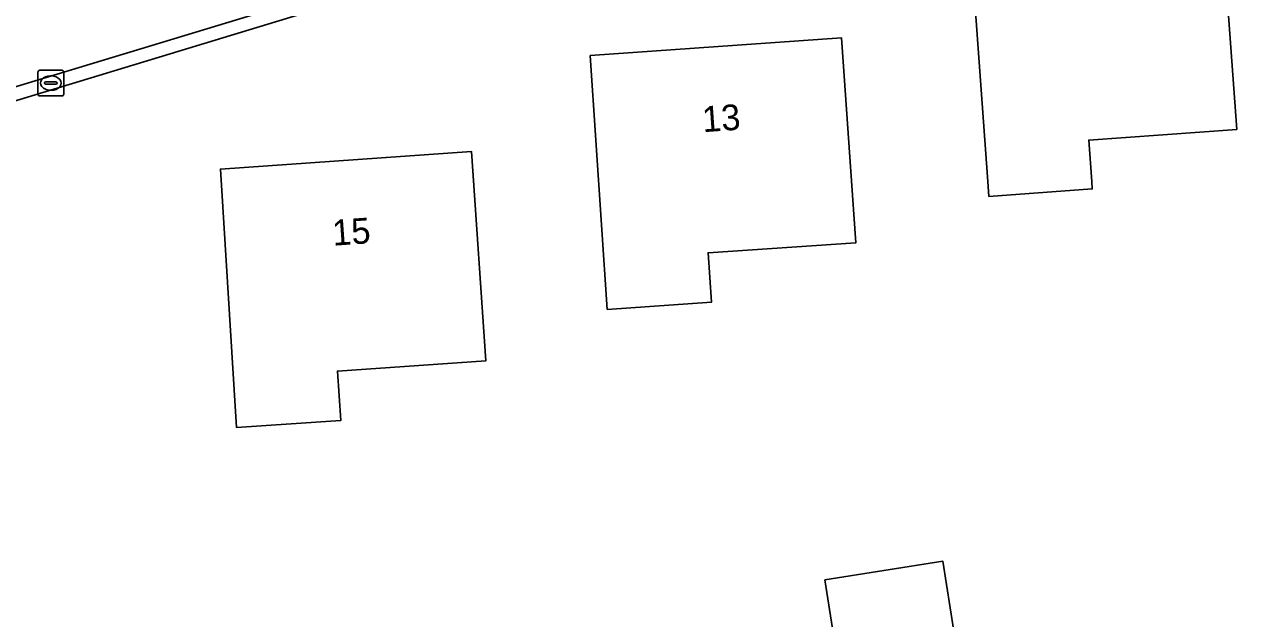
# Model space of a CAD drawing. Extents: x 162661 to 163484, y 380247 to 381230.
# Drawn here: x 162936.22 to 162983.36, y 380733 to 380756.11 of the extents above; entities that cross this region are included whole.
import ezdxf

# ---------------------------------------------------------------- set-up
doc = ezdxf.new("R2010")
doc.units = 0
for name, color, linetype in [('IMGEO_Erf', 7, 'Continuous'), ('IMGEO_Kolk', 7, 'Continuous'), ('IMGEO_Pand', 7, 'Continuous'), ('IMGEO_Pand_nummerreeks', 7, 'Continuous'), ('IMGEO_Rijbaan_lokaal_gesloten', 7, 'Continuous'), ('IMGEO_Rijbaan_lokaal_open', 7, 'Continuous')]:
    doc.layers.add(name, color=color, linetype=linetype)

msp = doc.modelspace()

# ---------------------------------------------------------------- linework, layer by layer
at = {"layer": 'IMGEO_Erf'}
for points in [[(162973.731, 380749.423), (162973.689, 380750), (162973.017, 380759.297), (162982.788, 380760.004), (162983.365, 380752.025), (162977.61, 380751.608), (162977.729, 380750), (162977.75, 380749.714)], [(162958.892, 380745.029), (162958.226, 380754.895), (162967.998, 380755.581), (162968.557, 380747.619), (162962.812, 380747.229), (162962.943, 380745.304)], [(162948.397, 380742.631), (162948.527, 380740.706), (162944.477, 380740.431), (162943.85, 380750.482), (162953.611, 380751.168), (162954.164, 380743.023)], [(162967.354, 380734.516), (162971.941, 380735.24), (162972.514, 380731.609), (162969.108, 380731.072), (162968.872, 380732.568), (162967.691, 380732.382)]]:
    msp.add_lwpolyline(points, close=True, dxfattribs=at)
msp.add_lwpolyline([(162954.012, 380758.66), (162897.8, 380741.576), (162880.446, 380736.315), (162878.841, 380735.907), (162876.106, 380735.042)], dxfattribs=at)
at = {"layer": 'IMGEO_Kolk'}
for p, q in [((162936.756, 380753.4), (162936.756, 380754.252)), ((162936.831, 380754.326), (162937.683, 380754.326)), ((162937.757, 380754.252), (162937.757, 380753.4)), ((162937.015, 380753.82), (162937.015, 380753.832)), ((162937.453, 380753.783), (162937.055, 380753.783)), ((162937.058, 380753.869), (162937.456, 380753.869)), ((162937.244, 380754.106), (162937.269, 380754.106)), ((162937.499, 380753.832), (162937.499, 380753.82)), ((162937.683, 380753.326), (162936.831, 380753.326)), ((162937.267, 380753.546), (162937.242, 380753.546))]:
    msp.add_line(p, q, dxfattribs=at)
for points in [[(162936.756, 380753.4), (162936.756, 380754.252)], [(162936.831, 380754.326), (162937.683, 380754.326)], [(162937.757, 380754.252), (162937.757, 380753.4)], [(162937.683, 380753.326), (162936.831, 380753.326)]]:
    msp.add_lwpolyline(points, dxfattribs=at)
for centre, radius, start, end in [((162936.833, 380754.25), 0.0765, 91.552, 178.448), ((162936.833, 380754.25), 0.0765, 91.552, 178.448), ((162937.681, 380754.25), 0.0765, 1.552, 88.448), ((162937.681, 380754.25), 0.0765, 1.552, 88.448), ((162937.055, 380753.829), 0.0403, 85.8775, 175.7526), ((162937.052, 380753.819), 0.0366, 178.938, 274.7102), ((162937.456, 380753.826), 0.043, 264.8664, 352.4533), ((162937.46, 380753.831), 0.0386, 1.7309, 96.639), ((162936.833, 380753.402), 0.0765, 181.552, 268.448), ((162936.833, 380753.402), 0.0765, 181.552, 268.448), ((162937.681, 380753.402), 0.0765, 271.552, 358.448), ((162937.681, 380753.402), 0.0765, 271.552, 358.448)]:
    msp.add_arc(centre, radius, start, end, dxfattribs=at)
for centre, major_axis, ratio, start_param, end_param in [((162937.243, 380753.826), (-0.387, 0.002), 0.722429, 4.712389, 7.853982), ((162937.268, 380753.826), (-0.39, 0.002), 0.717154, 1.570796, 4.712389)]:
    msp.add_ellipse(centre, major_axis=major_axis, ratio=ratio, start_param=start_param, end_param=end_param, dxfattribs=at)
at = {"layer": 'IMGEO_Pand'}
for points in [[(162973.731, 380749.423), (162977.75, 380749.714), (162977.729, 380750), (162977.61, 380751.608), (162983.365, 380752.025), (162982.788, 380760.004), (162973.017, 380759.297), (162973.689, 380750)], [(162958.892, 380745.029), (162962.943, 380745.304), (162962.812, 380747.229), (162968.557, 380747.619), (162967.998, 380755.581), (162958.226, 380754.895)], [(162944.477, 380740.431), (162948.527, 380740.706), (162948.397, 380742.631), (162954.164, 380743.023), (162953.611, 380751.168), (162943.85, 380750.482)], [(162967.354, 380734.516), (162967.691, 380732.382), (162968.872, 380732.568), (162969.108, 380731.072), (162972.514, 380731.609), (162971.941, 380735.24)]]:
    msp.add_lwpolyline(points, close=True, dxfattribs=at)
at = {"layer": 'IMGEO_Rijbaan_lokaal_gesloten'}
msp.add_lwpolyline([(162943.853, 380759.265), (162942.012, 380760.182), (162860.899, 380735.613), (162859.794, 380735.265), (162861.104, 380731.004), (162867.044, 380732.815), (162867.469, 380732.943), (162875.325, 380735.325), (162875.852, 380735.497), (162899.799, 380742.755), (162955.124, 380759.519), (162956.082, 380761.304)], dxfattribs=at)
at = {"layer": 'IMGEO_Rijbaan_lokaal_open'}
msp.add_lwpolyline([(162955.124, 380759.519), (162899.799, 380742.755), (162875.852, 380735.497), (162876.106, 380735.042), (162878.841, 380735.907), (162880.446, 380736.315), (162897.8, 380741.576), (162954.012, 380758.66)], dxfattribs=at)

# ---------------------------------------------------------------- texts
at = {"layer": 'IMGEO_Pand_nummerreeks'}
for s, rotation, p in [('13', 4.0159, (162962.612, 380751.915)), ('15', 4.0184, (162948.23, 380747.502))]:
    msp.add_text(s, height=1, rotation=rotation, dxfattribs=at).set_placement(p)

doc.saveas('drawing.dxf')
